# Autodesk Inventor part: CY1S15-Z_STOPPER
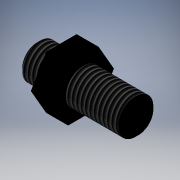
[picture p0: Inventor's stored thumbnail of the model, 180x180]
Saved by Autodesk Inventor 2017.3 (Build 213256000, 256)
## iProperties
Part Number: CY1S15-Z_STOPPER
Material: Generic
Catalog Web Link: www.cadenas.de
Description: CY1S-Z_STOPPER-Magnetically Coupled Rodless Cylinder Slider Type/Slide Bearing
Vendor: SMC
Document SubType Name: Modeling
Designer: partserver
Manufacturer: SMC
Mass: 1.53384 g
Surface Area: 9.01352 cm^2
Volume: 1.53384 cm^3
Density: 1 g/cm^3
Appearance: PSOLRGB-0-0-0
Category: PARTsolutions
Company: SMC
Title: CY1S15-Z_STOPPER
Author: Cadenas PARTsolutions
Comments: Magnetically Coupled Rodless Cylinder Slider Type/Slide Bearing
PSOL_IDENT_0: {$CADENAS_DATA\23d-libs\smc_jp\actuator\rodless_cylinders\cy1\cy1s_z\parts\cy1s_z_stopper.prj},180 {
PSOL_IDENT_1: VTYP=3D},{NB=CY1S15-Z_STOPPER},{LINA=CY1S15-Z_STOPPER},{NN=CY1S-Z_STOPPER},{DATE=09.12.2020 02:54:14
PSOL_IDENT_2: },{GEOMDATE=09.03.2020 08:58:35},{VERSION=},{LINEID=30},{WBVAR=},{WBNUMERIC=}  {NB=CY1S15-Z_STOPPER}
PSOL_IDENT_3: ,{LINA=CY1S15-Z_STOPPER},{KT=DUMMY},{BORE=15},{UU=M8x1},{UURA=8.000},{UURP=1.000},{NA=10.500},{R=1.0
PSOL_IDENT_4: 00},{T=12.500},{A1=4.400},{A2=12.000},{A3=4.000},{R1=5.500},{THREAD2=MIN},{POS=MIN},{STOP=MIN}
NB: CY1S15-Z_STOPPER
NN: CY1S-Z_STOPPER
NT: Magnetically Coupled Rodless Cylinder Slider Type/Slide Bearing
NBSYN: CY1S$BORE.-Z_STOPPER
LINA: CY1S15-Z_STOPPER
CATALOG: SMC (JP
BORE: 15
UU: M8x1
UURA: 8
UURP: 1
NA: 10.5
R: 1
T: 12.5
A1: 4.4
A2: 12
A3: 4
R1: 5.5
THREAD2: 0
POS: 0
STOP: 0
SUPPLIER: SMC
ARTICLENO: CY1S15-Z_STOPPER
BOMINFO: CY1S15-Z_STOPPER
CREATOR: CADENAS GmbH
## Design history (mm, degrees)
sketch "Sketch_1"
  geometry: L1 (10.5, 0)-(-13.5, 0); L2 (-13.5, 0)-(-13.5, 1.7); L3 (-13, 2.2)-(-12.5, 2.2); L4 (-12.5, 2.2)-(-12.5, 3.386); L5 (-12.5, 3.386)-(-11.886, 4); L6 (-11.886, 4)-(9.886, 4); L7 (9.886, 4)-(10.5, 3.386); L8 (10.5, 3.386)-(10.5, 0); L9 (10.5, 0)-(-13.5, 0); A1 r 0.5 centre (-13, 1.7) between (-13, 2.2) and (-13.5, 1.7)
  constraints: 18 end point, 2 point on circle, 1 centre point
revolve "Revolution1" sketch "Sketch_1" stored, may be unused: angle "d0" = 360 deg
thread "Thread1" dims "d1" = 21.773, "d2" = 0
sketch "Sketch_2"
  geometry: L1 (-3.464, 6)-(-6.928, 0); L2 (-6.928, 0)-(-3.464, -6); L3 (-3.464, -6)-(3.464, -6); L4 (3.464, -6)-(6.928, 0); L5 (6.928, 0)-(3.464, 6); L6 (3.464, 6)-(-3.464, 6)
  constraints: 12 end point
extrude "Extrusion1" join sketch "Sketch_2" distance "d3" = 5; taper "d4" = 0 deg
node "STOOPER_CT_XY"
node "STOOPER_CT_YZ"
node "STOOPER_CT_ZX"
node "STOOPER_CT_X"
node "STOOPER_CT_Y"
node "STOOPER_CT_Z"
node "STOOPER_CT_Center"
body "Solid1"
other parameters: "d5" = 0
